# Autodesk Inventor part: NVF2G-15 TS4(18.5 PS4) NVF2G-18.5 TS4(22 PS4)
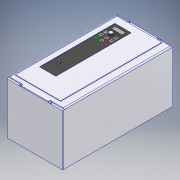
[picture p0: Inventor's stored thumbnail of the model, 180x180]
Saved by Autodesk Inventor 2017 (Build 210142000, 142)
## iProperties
Part Number: NVF2G-15 TS4(18.5 PS4) NVF2G-18.5 TS4(22 PS4)
Material: Типовые
Document SubType Name: Modeling
Designer: RSagdiev
Density: 1 g/cm^3
Appearance: По умолчанию
Author: RSagdiev
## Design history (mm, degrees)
sketch "Эскиз1"
  geometry: L1 (0, 0)-(44.679, 0) reference; L2 (0, 0)-(0, 56.035) reference; L3 (0, 0)-(426, 0); L4 (426, 0)-(426, 197.6); L5 (426, 197.6)-(0, 197.6); L6 (0, 197.6)-(0, 0)
  constraints: 12 end point, 3 horizontal, 2 parallel, 2 vertical, 1 perpendicular
  dimensions: "d0" = 426 distance of L5.end L4.end; "d1" = 197.6 distance of L4.end L3.end
extrude "Выдавливание1" new body sketch "Эскиз1" stored distance "d2" = 215; taper "d3" = 0 deg
sketch "Эскиз2"
  geometry: L1 (0, 0)-(0, 426) reference; L2 (215, 0)-(215, 426) reference; L3 (0, 426)-(55, 426); L4 (215, 426)-(215, 419); L5 (215, 0)-(160, 0); L6 (0, 0)-(0, 7); L7 (0, 426)-(215, 426) reference; L8 (0, 426)-(55, 426); L9 (55, 426)-(55, 419); L10 (55, 419)-(0, 419); L11 (0, 419)-(0, 426); L12 (215, 426)-(160, 426); L13 (160, 426)-(160, 419); L14 (160, 419)-(215, 419); L15 (215, 419)-(215, 426); L16 (0, 0)-(215, 0) reference; L17 (0, 0)-(55, 0); L18 (55, 0)-(55, 7); L19 (55, 7)-(0, 7); L20 (0, 7)-(0, 0); L21 (215, 0)-(160, 0); L22 (160, 0)-(160, 7); L23 (160, 7)-(215, 7); L24 (215, 7)-(215, 0); L25 (55, 426)-(160, 426); L26 (0, 419)-(0, 426); L27 (160, 426)-(215, 426); L28 (215, 419)-(215, 7); L29 (160, 0)-(55, 0); L30 (215, 7)-(215, 0); L31 (55, 0)-(0, 0); L32 (0, 7)-(0, 419); 1 further point
  constraints: 56 end point, 26 parallel, 13 perpendicular, 7 horizontal
  dimensions: "d4" = 55 distance of L9.end L10.end; "d5" = 7 distance of L3.end L9.end; "d6" = 55 distance of L4.end L13.end; "d7" = 7 distance of L13.end L12.end; "d8" = 55 distance of L6.end L18.end; "d9" = 7 distance of L18.end L17.end; "d10" = 55 distance of L22.end L23.end; "d11" = 7 distance of L5.end L22.end
extrude "Выдавливание2" new body sketch "Эскиз2" distance "d12" = 4; taper "d13" = 0 deg
chamfer "Фаска1" distance "d14" = 4; stored, may be unused: second distance "d15" = 2, angle "d16" = 45 deg
sketch "Эскиз3"
  geometry: L1 (184.042, 23.143)-(184.042, 413.729); L2 (12.485, 413.729)-(184.042, 413.729); L3 (10.042, 413.729)-(10.042, 23.143); L4 (10.042, 413.729)-(184.042, 413.729); L5 (10.042, 23.143)-(184.042, 23.143); L6 (55, 422)-(160, 422) reference; L7 (55, 0)-(160, 0) reference; L8 (0, 419)-(0, 7) reference; L9 (215, 7)-(215, 419) reference; 1 further point
  constraints: 11 end point, 2 perpendicular, 1 horizontal, 1 point on line
  dimensions: "d160" = 8.27064 distance between parallel lines of L4 L6; "d161" = 23.14275 distance between parallel lines of L7 L5; "d162" = 10.04205 distance between parallel lines of L8 L3; "d164" = 30.95795 distance between parallel lines of L9 L1
extrude "Выдавливание3" new body sketch "Эскиз3" distance "d17" = 2; taper "d18" = 0 deg
sketch "Эскиз4"
  geometry: L1 (91, 386)-(32, 386); L2 (30, 384)-(30, 98); L3 (32, 96)-(91, 96); L4 (93, 98)-(93, 384); L5 (0, 426)-(215, 426) reference; L6 (0, 419)-(0, 7) reference; A1 r 2 centre (32, 384) between (32, 386) and (30, 384); A2 r 2 centre (91, 384) between (93, 384) and (91, 386); A3 r 2 centre (91, 98) between (91, 96) and (93, 98); A4 r 2 centre (32, 98) between (30, 98) and (32, 96); 6 further points
  constraints: 8 end point, 8 point on circle, 8 tangent, 6 point on line, 4 centre point, 3 equal radius, 2 parallel, 1 horizontal, 1 perpendicular
  dimensions: "d20" = 63 distance of point (93, 96) point (30, 96); "d21" = 290 distance of point (30, 96) point (30, 386); "d24" = 2 radius of A1; "d165" = 40 distance between parallel lines of L5 L1; "d166" = 30 distance between parallel lines of L6 L2
extrude "Выдавливание4" cut sketch "Эскиз4" distance "d25" = 0.6; taper "d26" = 0 deg
sketch "Эскиз5"
  geometry: L1 (0, 426)-(215, 426) reference; L2 (0, 0)-(0, 426) reference; L3 (215, 426)-(215, 0) reference; L4 (0, 0)-(215, 0) reference; C1 r 2.5 at (47.5, 422.5); C2 r 2.5 at (167.5, 422.5); C3 r 2.5 at (47.5, 3.5); C4 r 2.5 at (167.5, 3.5); 1 further point
  constraints: 4 centre point
  dimensions: "d27" = 5 diameter of C1; "d28" = 3.5 distance from line of C1.centre L1; "d30" = 5 diameter of C2; "d31" = 3.5 distance from line of C2.centre L1; "d33" = 5 diameter of C3; "d34" = 3.5 distance from line of L4 C3.centre; "d36" = 5 diameter of C4; "d38" = 3.5 distance from line of C4.centre L4; "d169" = 120 distance of C1.centre C2.centre; "d170" = 47.5 distance from line of L3 C2.centre; "d171" = 47.5 distance from line of L2 C1.centre (derived); "d172" = 120 distance of C4.centre C3.centre (derived); "d173" = 47.5 distance from line of L3 C4.centre (derived)
extrude "Выдавливание5" cut sketch "Эскиз5" stored distance "d39" = 0.6; taper "d40" = 0 deg
sketch "Эскиз6"
  geometry: L1 (30, 295)-(30, 351); L2 (93.748, 293)-(32, 293); L3 (93, 384)-(93, 351); L4 (32, 386)-(91, 386); L5 (30, 295)-(30, 384); L6 (30, 351)-(93, 351); L7 (93, 384)-(93, 289.118); L8 (30, 351)-(30, 384); L9 (93, 351)-(93, 289.118); L10 (43.5, 362)-(79.5, 362); L11 (81.5, 364)-(81.5, 374); L12 (79.5, 376)-(43.5, 376); L13 (41.5, 374)-(41.5, 364); L14 (41.5, 362)-(81.5, 376); L15 (81.5, 362)-(41.5, 376); L16 (61.5, 339.5)-(61.5, 304.857); L17 (53.25, 339.5)-(53.25, 304.857); L18 (69.75, 304.857)-(69.75, 339.5); L19 (47, 346)-(36, 346); L20 (35, 345)-(35, 334); L21 (36, 333)-(47, 333); L22 (48, 334)-(48, 345); L23 (48, 346)-(35, 333); L24 (35, 346)-(48, 333); L25 (81.5, 364)-(81.5, 299.5); L26 (41.5, 339.5)-(88.409, 339.5); L27 (39.654, 322.179)-(85.729, 322.179); L28 (39.654, 304.857)-(84.963, 304.857); L29 (88, 334)-(88, 345); L30 (76, 333)-(87, 333); L31 (88, 346)-(75, 333); L32 (75, 346)-(88, 333); L33 (75, 345)-(75, 334); L34 (87, 346)-(76, 346); L35 (88, 316.679)-(88, 327.679); L36 (76, 315.679)-(87, 315.679); L37 (88, 328.679)-(75, 315.679); L38 (75, 328.679)-(88, 315.679); L39 (75, 327.679)-(75, 316.679); L40 (87, 328.679)-(76, 328.679); L41 (88, 299.357)-(88, 310.357); L42 (76, 298.357)-(87, 298.357); L43 (88, 311.357)-(75, 298.357); L44 (75, 311.357)-(88, 298.357); L45 (75, 310.357)-(75, 299.357); L46 (87, 311.357)-(76, 311.357); L47 (48, 299.357)-(48, 310.357); L48 (36, 298.357)-(47, 298.357); L49 (48, 311.357)-(35, 298.357); L50 (35, 311.357)-(48, 298.357); L51 (35, 310.357)-(35, 299.357); L52 (47, 311.357)-(36, 311.357); L53 (48, 316.679)-(48, 327.679); L54 (36, 315.679)-(47, 315.679); L55 (48, 328.679)-(35, 315.679); L56 (35, 328.679)-(48, 315.679); L57 (35, 327.679)-(35, 316.679); L58 (47, 328.679)-(36, 328.679); L59 (93.748, 293)-(32, 293); L60 (93, 334.729)-(93, 289.118); L61 (0, 426)-(215, 426) reference; L62 (0, 417)-(0, 9) reference; C1 r 6.5 at (61.5, 339.5); C2 r 6.5 at (61.5, 304.857); C3 r 6.5 at (61.5, 322.179); A1 r 2 centre (43.5, 374) between (43.5, 376) and (41.5, 374); A2 r 2 centre (79.5, 374) between (81.5, 374) and (79.5, 376); A3 r 2 centre (79.5, 364) between (79.5, 362) and (81.5, 364); A4 r 2 centre (43.5, 364) between (41.5, 364) and (43.5, 362); A5 r 8.25 centre (61.5, 339.5) between (69.75, 339.5) and (53.25, 339.5); A6 r 8.25 centre (61.5, 304.857) between (53.25, 304.857) and (69.75, 304.857); A7 r 1 centre (47, 345) between (48, 345) and (47, 346); A8 r 1 centre (47, 334) between (47, 333) and (48, 334); A9 r 1 centre (36, 334) between (35, 334) and (36, 333); A10 r 1 centre (36, 345) between (36, 346) and (35, 345); A11 r 1 centre (87, 334) between (87, 333) and (88, 334); A12 r 1 centre (87, 345) between (88, 345) and (87, 346); A13 r 1 centre (76, 345) between (76, 346) and (75, 345); A14 r 1 centre (76, 334) between (75, 334) and (76, 333); A15 r 1 centre (87, 316.679) between (87, 315.679) and (88, 316.679); A16 r 1 centre (87, 327.679) between (88, 327.679) and (87, 328.679); A17 r 1 centre (76, 327.679) between (76, 328.679) and (75, 327.679); A18 r 1 centre (76, 316.679) between (75, 316.679) and (76, 315.679); A19 r 1 centre (87, 299.357) between (87, 298.357) and (88, 299.357); A20 r 1 centre (87, 310.357) between (88, 310.357) and (87, 311.357); A21 r 1 centre (76, 310.357) between (76, 311.357) and (75, 310.357); A22 r 1 centre (76, 299.357) between (75, 299.357) and (76, 298.357); A23 r 1 centre (47, 299.357) between (47, 298.357) and (48, 299.357); A24 r 1 centre (47, 310.357) between (48, 310.357) and (47, 311.357); A25 r 1 centre (36, 310.357) between (36, 311.357) and (35, 310.357); A26 r 1 centre (36, 299.357) between (35, 299.357) and (36, 298.357); A27 r 1 centre (47, 316.679) between (47, 315.679) and (48, 316.679); A28 r 1 centre (47, 327.679) between (48, 327.679) and (47, 328.679); A29 r 1 centre (36, 327.679) between (36, 328.679) and (35, 327.679); A30 r 1 centre (36, 316.679) between (35, 316.679) and (36, 315.679); A31 r 2 centre (32, 384) between (32, 386) and (30, 384); A32 r 2 centre (91, 384) between (93, 384) and (91, 386); A33 r 2 centre (93.671, 291.001) between (93.748, 293) and (93, 289.118); A34 r 2 centre (32, 295) between (30, 295) and (32, 293); 15 further points
  constraints: 122 end point, 68 point on circle, 68 point on line, 66 tangent, 37 centre point, 21 equal radius, 15 midpoint, 15 parallel, 11 horizontal, 7 collinear, 7 perpendicular, 3 coincident, 2 vertical
  dimensions: "d43" = 35 distance between parallel lines of L4 L6; "d44" = 40 distance of L15.end L14.end; "d45" = 14 distance of L14.end L15.start; "d46" = 10 distance between parallel lines of L4 L12; "d47" = 2 radius of A1; "d48" = 11.5 distance between parallel lines of L8 L13; "d49" = 16.5 diameter of A6; "d50" = 31.5 distance between parallel lines of L1 L16; "d51" = 11.5 distance from line of L6 L16.start; "d52" = 11.85714 distance from line of L2 L16.end; "d53" = 13 diameter of C1; "d54" = 13 diameter of C2; "d55" = 13 diameter of C3; "d56" = 13 distance of L24.end L23.end; "d57" = 13 distance of L23.end L24.start; "d58" = 1 radius of A7 (derived); "d59" = 11.5 distance from line of L6 L26.start; "d60" = 11.5 distance from line of L5 L26.start; "d61" = 13 distance of L32.end L31.end; "d62" = 13 distance of L31.end L32.start; "d63" = 1 radius of A12 (derived); "d64" = 13 distance of L38.end L37.end; "d65" = 13 distance of L37.end L38.start; "d66" = 1 radius of A16 (derived); "d67" = 13 distance of L44.end L43.end; "d68" = 13 distance of L43.end L44.start; "d69" = 1 radius of A20 (derived); "d70" = 13 distance of L50.end L49.end; "d71" = 13 distance of L49.end L50.start; "d72" = 1 radius of A24 (derived); "d73" = 13 distance of L56.end L55.end; "d74" = 13 distance of L55.end L56.start; "d75" = 1 radius of A28 (derived); "d146" = 40 distance of point (81.5, 339.5) L26.start; "d147" = 4.32143 distance between parallel lines of L40 L30; "d148" = 4.32143 distance between parallel lines of L46 L36; "d149" = 93 distance between parallel lines of L2 L4; "d150" = 63 distance between parallel lines of L60 L1; "d151" = 2 radius of A31; "d152" = 2 radius of A32; "d153" = 2 radius of A33; "d154" = 2 radius of A34; "d167" = 40 distance between parallel lines of L4 L61 (derived); "d168" = 30 distance between parallel lines of L62 L5 (derived)
extrude "Выдавливание6" new body sketch "Эскиз6" distance "d76" = 0.3; taper "d77" = 0 deg
extrude "Выдавливание7" new body sketch "Эскиз6" distance "d78" = 0.6; taper "d79" = 0 deg
sketch "Эскиз7"
  geometry: L1 (30, 351)-(93, 351) reference; L2 (30, 351)-(93, 351); L3 (93, 351)-(93, 351.1); L4 (93, 351.1)-(30, 351.1); L5 (30, 351.1)-(30, 351); 4 further points; 1 other entity
  constraints: 8 end point, 2 parallel, 1 horizontal, 1 perpendicular, 2 other
  dimensions: "d80" = 0.1 distance of L3.end L2.end
extrude "Выдавливание8" cut sketch "Эскиз7" distance "d81" = 0.3; taper "d82" = 0 deg
sketch "Эскиз8" dims "d91" = 10
  geometry: C1 r 1 at (38, 356.1); C2 r 1 at (45.75, 356.1); C3 r 1 at (53.5, 356.1); C4 r 1 at (61.25, 356.1); C5 r 1 at (69, 356.1); C6 r 1 at (76.75, 356.1); C7 r 1 at (84.5, 356.1); 7 further points; 2 other entities
  constraints: 7 centre point, 6 equal radius, 6 horizontal alignment, 2 other
  dimensions: "d83" = 2 diameter of C1; "d84" = 5 dimension on C1.centre; "d85" = 8 dimension on C1.centre; "d88" = 7.75 distance of C1.centre C2.centre
extrude "Выдавливание9" join sketch "Эскиз8" distance "d93" = 0.3; taper "d94" = 0 deg
sketch "Эскиз9"
  geometry: C1 r 6.5 at (0, 0) reference; C2 r 7.5 at (0, 0); 1 further point
  constraints: 1 centre point, 1 coincident
  dimensions: "d95" = 15 diameter of C2
extrude "Выдавливание10" join sketch "Эскиз9" distance "d96" = 9.4; taper "d97" = -3 deg
sketch "Эскиз10"
  geometry: L1 (0, 7.331)-(0.619, 6.259); L2 (0.619, 6.259)-(-0.619, 6.259); L3 (-0.619, 6.259)-(0, 7.331); 2 further points
  constraints: 6 end point, 7 other
sketch "Эскиз11"
  geometry: L1 (0, 7.917)-(0.884, 6.386); L2 (0.884, 6.386)-(-0.884, 6.386); L3 (-0.884, 6.386)-(0, 7.917); 2 further points
  constraints: 6 end point, 7 other
feature "Лофт1" sketch "Эскиз10", "Эскиз11" dims "d98" = 0, "d99" = 90 deg, "d100" = 0, "d101" = 90 deg
sketch "Эскиз12"
  geometry: L1 (38.421, 341.665)-(44.641, 341.665); L2 (44.641, 341.665)-(44.641, 338.165); L3 (44.641, 338.165)-(38.421, 338.165); L4 (38.421, 338.165)-(38.421, 341.665); L5 (37.471, 324.566)-(46.326, 324.566); L6 (46.326, 324.566)-(46.326, 320.935); L7 (46.326, 320.935)-(37.471, 320.935); L8 (37.471, 320.935)-(37.471, 324.566); L9 (37.115, 307.229)-(46.472, 307.229); L10 (46.472, 307.229)-(46.472, 303.655); L11 (46.472, 303.655)-(37.115, 303.655); L12 (37.115, 303.655)-(37.115, 307.229); L13 (75.944, 307.229)-(87.496, 307.229); L14 (87.496, 307.229)-(87.496, 303.582); L15 (87.496, 303.582)-(75.944, 303.582); L16 (75.944, 303.582)-(75.944, 307.229); L17 (77.725, 324.447)-(85.919, 324.447); L18 (85.919, 324.447)-(85.919, 320.822); L19 (85.919, 320.822)-(77.725, 320.822); L20 (77.725, 320.822)-(77.725, 324.447); L21 (75.825, 341.783)-(88.875, 341.783); L22 (88.875, 341.783)-(88.875, 338.159); L23 (88.875, 338.159)-(75.825, 338.159); L24 (75.825, 338.159)-(75.825, 341.783); 1 further point
  constraints: 12 other
feature "Рельеф1" dims "d105" = 0.1, "d106" = 0
feature "Рельеф2" dims "d107" = 0.1, "d108" = 0
feature "Рельеф3" dims "d109" = 0.1, "d110" = 0
feature "Рельеф4" dims "d111" = 0.1, "d112" = 0
feature "Рельеф5" dims "d113" = 0.1, "d114" = 0
feature "Рельеф6" dims "d115" = 0.1, "d116" = 0
sketch "Эскиз13"
  geometry: L1 (-3.144, -2.347)-(-0.04, 3.728); L2 (-0.04, 3.728)-(3.298, -2.347); L3 (3.298, -2.347)-(2.096, -2.347); L4 (2.096, -2.347)-(-0.04, 1.541); L5 (-0.04, 1.541)-(-2.027, -2.347); L6 (-2.027, -2.347)-(-3.144, -2.347); L7 (-9.387, -8.657)-(8.031, -8.657); L8 (-3.144, -14.967)-(-0.04, -21.041); L9 (-0.04, -21.041)-(3.298, -14.967); L10 (3.298, -14.967)-(2.096, -14.967); L11 (2.096, -14.967)-(-0.04, -18.855); L12 (-0.04, -18.855)-(-2.027, -14.967); L13 (-2.027, -14.967)-(-3.144, -14.967); 1 further point
  constraints: 26 end point, 6 symmetric about line, 2 horizontal, 2 parallel, 2 point on line, 1 collinear
feature "Рельеф7" dims "d117" = 0.1, "d118" = 0
feature "Рельеф8" dims "d119" = 0.1, "d120" = 0
sketch "Эскиз14"
  geometry: L1 (58.847, 155.147)-(67.143, 140.777); L2 (67.143, 140.777)-(50.55, 140.777); L3 (50.55, 140.777)-(58.847, 155.147); L4 (65.716, 141.601)-(58.847, 153.499); L5 (58.847, 153.499)-(51.977, 141.601); L6 (51.977, 141.601)-(65.716, 141.601); L7 (58.02, 149.832)-(57.079, 146.022); L8 (57.079, 146.022)-(59.5, 146.192); L9 (59.5, 146.192)-(58.459, 143.876); L10 (58.459, 143.876)-(57.51, 144.303); L11 (57.51, 144.303)-(57.666, 142.072); L12 (57.666, 142.072)-(60.137, 143.122); L13 (60.137, 143.122)-(59.456, 143.428); L14 (59.456, 143.428)-(61.385, 147.064); L15 (61.385, 147.064)-(58.23, 146.881); L16 (58.23, 146.881)-(59.796, 149.832); L17 (59.796, 149.832)-(58.02, 149.832); 2 further points
  constraints: 34 end point, 2 perpendicular, 2 point on line, 1 parallel, 9 other
extrude "Выдавливание11" cut sketch "Эскиз14" distance "d121" = 0.8; taper "d122" = 0 deg
extrude "Выдавливание12" join sketch "Эскиз14" stored distance "d123" = 0.05; taper "d124" = 0 deg
sketch "Эскиз15"
  geometry: L1 (32.937, 360.41)-(56.853, 360.41); L2 (56.853, 360.41)-(56.853, 357.81); L3 (56.853, 357.81)-(32.937, 357.81); L4 (32.937, 357.81)-(32.937, 360.41); L5 (58.162, 359.617)-(88.881, 359.617); L6 (88.881, 359.617)-(88.881, 355.704); L7 (88.881, 355.704)-(58.162, 355.704); L8 (58.162, 355.704)-(58.162, 359.617); C1 r 1 at (38, 356.1) reference; 10 further points; 3 other entities
  constraints: 7 other
  dimensions: "d155" = 0.71019 distance edge to line of C1 L3; "d156" = 2.93695 dimension on L4; "d157" = 4.60387 dimension on L7; "d158" = 4.11868 dimension on L6
feature "Рельеф9" sketch "Эскиз15" dims "d125" = 0.1, "d126" = 0
sketch "Эскиз17"
  geometry: L1 (54.534, 359)-(54.534, 352.001); L2 (54.534, 352.001)-(52.465, 352.001); L3 (52.465, 352.001)-(52.465, 359); L4 (52.465, 359)-(54.534, 359); 1 further point
  constraints: 2 other
feature "Рельеф10" sketch "Эскиз17" dims "d144" = 0.1, "d145" = 0
sketch "Эскиз19" dims "d179" = 10
  geometry: L1 (113.24, 333.958)-(134.375, 351.485); L2 (114.525, 332.409)-(135.66, 349.935); L3 (133.09, 353.034)-(111.955, 335.508); L4 (197.6, 419)-(197.6, 7) reference; L5 (113.24, 323.958)-(134.375, 341.485); L6 (114.525, 322.409)-(135.66, 339.935); L7 (133.09, 343.034)-(111.955, 325.508); L8 (113.24, 313.958)-(134.375, 331.485); L9 (114.525, 312.409)-(135.66, 329.935); L10 (133.09, 333.034)-(111.955, 315.508); L11 (113.24, 303.958)-(134.375, 321.485); L12 (114.525, 302.409)-(135.66, 319.935); L13 (133.09, 323.034)-(111.955, 305.508); L14 (113.24, 293.958)-(134.375, 311.485); L15 (114.525, 292.409)-(135.66, 309.935); L16 (133.09, 313.034)-(111.955, 295.508); L17 (113.24, 283.958)-(134.375, 301.485); L18 (114.525, 282.409)-(135.66, 299.935); L19 (133.09, 303.034)-(111.955, 285.508); L20 (113.24, 273.958)-(134.375, 291.485); L21 (114.525, 272.409)-(135.66, 289.935); L22 (133.09, 293.034)-(111.955, 275.508); L23 (113.24, 263.958)-(134.375, 281.485); L24 (114.525, 262.409)-(135.66, 279.935); L25 (133.09, 283.034)-(111.955, 265.508); L26 (113.24, 253.958)-(134.375, 271.485); L27 (114.525, 252.409)-(135.66, 269.935); L28 (133.09, 273.034)-(111.955, 255.508); L29 (113.24, 243.958)-(134.375, 261.485); L30 (114.525, 242.409)-(135.66, 259.935); L31 (133.09, 263.034)-(111.955, 245.508); A1 r 2.013 centre (113.24, 333.958) between (111.955, 335.508) and (114.525, 332.409); A2 r 2.013 centre (134.375, 351.485) between (135.66, 349.935) and (133.09, 353.034); A3 r 2.013 centre (113.24, 323.958) between (111.955, 325.508) and (114.525, 322.409); A4 r 2.013 centre (134.375, 341.485) between (135.66, 339.935) and (133.09, 343.034); A5 r 2.013 centre (113.24, 313.958) between (111.955, 315.508) and (114.525, 312.409); A6 r 2.013 centre (134.375, 331.485) between (135.66, 329.935) and (133.09, 333.034); A7 r 2.013 centre (113.24, 303.958) between (111.955, 305.508) and (114.525, 302.409); A8 r 2.013 centre (134.375, 321.485) between (135.66, 319.935) and (133.09, 323.034); A9 r 2.013 centre (113.24, 293.958) between (111.955, 295.508) and (114.525, 292.409); A10 r 2.013 centre (134.375, 311.485) between (135.66, 309.935) and (133.09, 313.034); A11 r 2.013 centre (113.24, 283.958) between (111.955, 285.508) and (114.525, 282.409); A12 r 2.013 centre (134.375, 301.485) between (135.66, 299.935) and (133.09, 303.034); A13 r 2.013 centre (113.24, 273.958) between (111.955, 275.508) and (114.525, 272.409); A14 r 2.013 centre (134.375, 291.485) between (135.66, 289.935) and (133.09, 293.034); A15 r 2.013 centre (113.24, 263.958) between (111.955, 265.508) and (114.525, 262.409); A16 r 2.013 centre (134.375, 281.485) between (135.66, 279.935) and (133.09, 283.034); A17 r 2.013 centre (113.24, 253.958) between (111.955, 255.508) and (114.525, 252.409); A18 r 2.013 centre (134.375, 271.485) between (135.66, 269.935) and (133.09, 273.034); A19 r 2.013 centre (113.24, 243.958) between (111.955, 245.508) and (114.525, 242.409); A20 r 2.013 centre (134.375, 261.485) between (135.66, 259.935) and (133.09, 263.034); 13 further points
  constraints: 80 end point, 40 point on circle, 20 centre point, 4 tangent, 1 midpoint, 1 parallel, 1 vertical, 108 other
  dimensions: "d176" = 10 distance of L2.start L6.start
extrude "Выдавливание14" cut sketch "Эскиз19" distance "d181" = 10; taper "d182" = 0 deg
sketch "Эскиз20" dims "d191" = 10, "d198" = 10
  geometry: L1 (197.6, 2)-(0, 2) reference; L2 (0, 426)-(0, 0) reference; C1 r 2 at (15, 132); C2 r 2 at (20, 132); C3 r 2 at (25, 132); C4 r 2 at (30, 132); C5 r 2 at (35, 132); C6 r 2 at (40, 132); C7 r 2 at (45, 132); C8 r 2 at (50, 132); C9 r 2 at (55, 132); C10 r 2 at (60, 132); C11 r 2 at (65, 132); C12 r 2 at (70, 132); C13 r 2 at (70, 127); C14 r 2 at (65, 127); C15 r 2 at (60, 127); C16 r 2 at (55, 127); C17 r 2 at (15, 127); C18 r 2 at (20, 127); C19 r 2 at (25, 127); C20 r 2 at (30, 127); C21 r 2 at (35, 127); C22 r 2 at (40, 127); C23 r 2 at (45, 127); C24 r 2 at (50, 127); C25 r 2 at (70, 122); C26 r 2 at (65, 122); C27 r 2 at (60, 122); C28 r 2 at (55, 122); C29 r 2 at (15, 122); C30 r 2 at (20, 122); C31 r 2 at (25, 122); C32 r 2 at (30, 122); C33 r 2 at (35, 122); C34 r 2 at (40, 122); C35 r 2 at (45, 122); C36 r 2 at (50, 122); C37 r 2 at (70, 117); C38 r 2 at (65, 117); C39 r 2 at (60, 117); C40 r 2 at (55, 117); C41 r 2 at (15, 117); C42 r 2 at (20, 117); C43 r 2 at (25, 117); C44 r 2 at (30, 117); C45 r 2 at (35, 117); C46 r 2 at (40, 117); C47 r 2 at (45, 117); C48 r 2 at (50, 117); C49 r 2 at (70, 112); C50 r 2 at (65, 112); C51 r 2 at (60, 112); C52 r 2 at (55, 112); C53 r 2 at (15, 112); C54 r 2 at (20, 112); C55 r 2 at (25, 112); C56 r 2 at (30, 112); C57 r 2 at (35, 112); C58 r 2 at (40, 112); C59 r 2 at (45, 112); C60 r 2 at (50, 112); C61 r 2 at (70, 107); C62 r 2 at (65, 107); C63 r 2 at (60, 107); C64 r 2 at (55, 107)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; 1 further point
  constraints: 240 centre point, 1 horizontal, 1 vertical, 478 other
  dimensions: "d183" = 4 diameter of C1; "d184" = 15 distance from line of L2 C1.centre; "d185" = 130 distance from line of L1 C1.centre; "d188" = 5 distance of C1.centre C2.centre; "d195" = 5 distance of C12.centre C13.centre
extrude "Выдавливание15" cut sketch "Эскиз20" distance "d200" = 15; taper "d201" = 0 deg
fillet "Сопряжение3" dims "d202" = 5
fillet "Сопряжение4" dims "d203" = 2
node "Твердое тело1"
pattern_circular "Круговой массив1" dims angle "d103" = 360 deg
node "Твердое тело2"
node "Твердое тело3"
node "Твердое тело4"
node "Твердое тело5"
